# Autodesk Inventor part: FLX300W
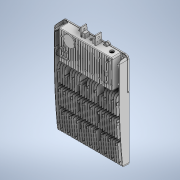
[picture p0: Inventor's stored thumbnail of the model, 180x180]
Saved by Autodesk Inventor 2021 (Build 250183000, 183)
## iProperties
Created: 2020-07
Part Number: FLX300W
Material: Generic
Description: STEP AP203
Document SubType Name: Modeling
Designer: DarrinWoodcock
Density: 1 g/cm^3
Appearance: Default
Title: FLK300W.STEP
Author: admin
Sending System: SolidWorks 2016
Preprocessor: SwSTEP 2.0
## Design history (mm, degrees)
feature "FLK300WÇ°¸Ç¿ªÄ£Í¼_20170730(1)_1:1"
feature "FLK300WÇ°¸Ç·ÀË®È¦´ò°åÍ¼-20170718_2:1"
feature "300W_3:1"
feature "300W_3:2"
feature "300W_3:3"
feature "300W_3:4"
feature "300W_3:5"
feature "300W_3:6"
feature "300W_3:7"
feature "300W_3:8"
feature "300W_3:9"
feature "300W_3:10"
feature "300W_3:11"
feature "300W_3:12"
feature "300W_3:13"
feature "300W_3:14"
feature "300W_3:15"
feature "300W_3:16"
feature "300W_3:17"
feature "300W_3:18"
feature "300W_3:19"
feature "300W_3:20"
feature "300W_3:21"
feature "300W_3:22"
feature "300W_3:23"
feature "300W_3:24"
feature "300W_3:25"
feature "300W_3:26"
feature "300W_3:27"
feature "300W_3:28"
feature "300W_3:29"
feature "300W_3:30"
feature "300W_3:31"
feature "300W_3:32"
feature "300W_3:33"
feature "300W_3:34"
feature "300W_3:35"
feature "300W_3:36"
feature "300W_3:37"
feature "300W_3:38"
feature "300W_3:39"
feature "300W_3:40"
feature "300W_3:41"
feature "300W_3:42"
feature "300W_3:43"
feature "170921-JYTL-FLK-126ºÏ1Í¸¾µ£¨ÎÞ¹âÑ§£©¼ÓÇ¿½î_4:1"
feature "170921-JYTL-FLK-126ºÏ1Í¸¾µ£¨ÎÞ¹âÑ§£©¼ÓÇ¿½î_5:1"
feature "170921-JYTL-FLK-126ºÏ1Í¸¾µ£¨ÎÞ¹âÑ§£©¼ÓÇ¿½î_6:1"
feature "°²×°Åä¼þ_7:1"
feature "°²×°Åä¼þ_8:1"
body "Solid1"
body "Solid2"
body "Solid3"
body "Solid4"
body "Solid5"
body "Solid6"
body "Solid7"
body "Solid8"
body "Solid9"
body "Solid10"
body "Solid11"
body "Solid12"
body "Solid13"
body "Solid14"
body "Solid15"
body "Solid16"
body "Solid17"
body "Solid18"
body "Solid19"
body "Solid20"
body "Solid21"
body "Solid22"
body "Solid23"
body "Solid24"
body "Solid25"
body "Solid26"
body "Solid27"
body "Solid28"
body "Solid29"
body "Solid30"
body "Solid31"
body "Solid32"
body "Solid33"
body "Solid34"
body "Solid35"
body "Solid36"
body "Solid37"
body "Solid38"
body "Solid39"
body "Solid40"
body "Solid41"
body "Solid42"
body "Solid43"
body "Solid44"
body "Solid45"
body "Solid46"
body "Solid47"
body "Solid48"
body "Solid49"
body "Solid50"
